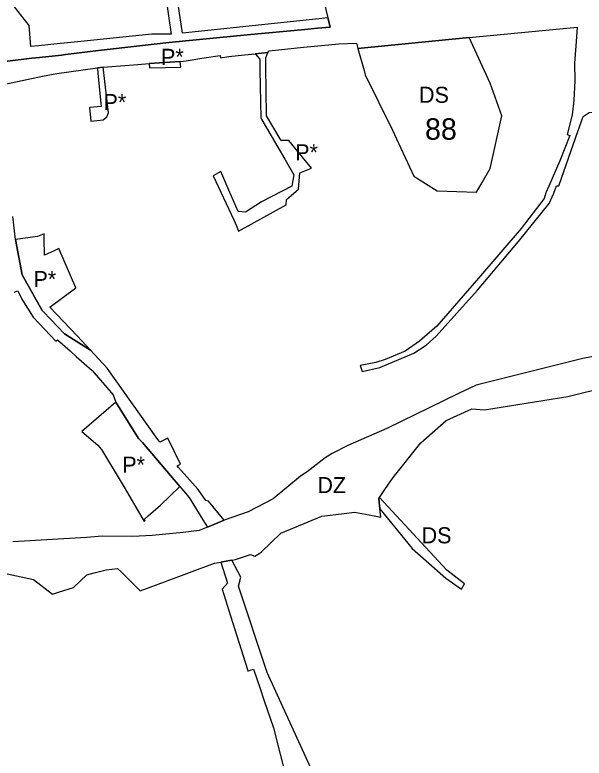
# Model space of a CAD drawing. Extents: x -477304 to -465641, y -1159113 to -1149285.
# Drawn here: x -475006.4 to -474687.6, y -1154553.8 to -1154137.8 of the extents above; entities that cross this region are included whole.
import ezdxf

# ---------------------------------------------------------------- set-up
doc = ezdxf.new("R2010")
doc.units = 0
for name, color, linetype in [('14', 7, 'Continuous'), ('22', 7, 'Continuous'), ('34', 7, 'Continuous'), ('35', 7, 'Continuous'), ('60', 7, 'Continuous')]:
    doc.layers.add(name, color=color, linetype=linetype)

msp = doc.modelspace()

# ---------------------------------------------------------------- linework, layer by layer
at = {"layer": '14'}
for p, q in [((-474752.01, -1154150.58), (-474814.35, -1154156.58)), ((-474814.35, -1154156.58), (-474810.87, -1154168.91)), ((-474810.87, -1154168.91), (-474810.16, -1154171.41)), ((-474810.16, -1154171.41), (-474795.13, -1154202.01)), ((-474795.13, -1154202.01), (-474783.06, -1154228.13)), ((-474783.06, -1154228.13), (-474769.99, -1154236.24)), ((-474769.99, -1154236.24), (-474747.97, -1154237.14))]:
    msp.add_line(p, q, dxfattribs=at)
msp.add_lwpolyline([(-474747.97, -1154237.14), (-474745.38, -1154232.64), (-474740.33, -1154223.86), (-474733.79, -1154194.37), (-474740.17, -1154176.02), (-474752.01, -1154150.58)], dxfattribs=at)
at = {"layer": '22'}
for p, q in [((-474636.13, -1154319.33), (-474688.28, -1154330.2)), ((-474688.28, -1154330.2), (-474748.09, -1154345.04)), ((-474748.09, -1154345.04), (-474757.89, -1154349.79)), ((-474757.89, -1154349.79), (-474798.19, -1154369.32)), ((-474798.19, -1154369.32), (-474819.91, -1154378.93)), ((-474819.91, -1154378.93), (-474828.71, -1154383.32)), ((-474832.7, -1154385.67), (-474842.67, -1154393.56)), ((-474828.71, -1154383.32), (-474832.7, -1154385.67)), ((-474842.67, -1154393.56), (-474846.54, -1154396.07)), ((-474846.54, -1154396.07), (-474861.86, -1154408.74)), ((-474802.64, -1154408.53), (-474802.25, -1154407.96)), ((-474861.86, -1154408.74), (-474875.74, -1154415.96)), ((-474801.95, -1154414.36), (-474802.64, -1154408.53)), ((-474875.74, -1154415.96), (-474889.28, -1154420.65)), ((-474801.42, -1154418.89), (-474801.95, -1154414.36)), ((-474889.28, -1154420.65), (-474898.52, -1154424.56)), ((-474834.49, -1154418.42), (-474822.1, -1154416.88)), ((-474808.03, -1154417.67), (-474801.42, -1154418.89)), ((-474912.16, -1154427.54), (-474929.44, -1154429.22)), ((-474966.39, -1154430.37), (-475007.64, -1154432.77)), ((-474957.5, -1154429.59), (-474966.39, -1154430.37)), ((-474940.42, -1154429.78), (-474957.5, -1154429.59)), ((-474929.44, -1154429.22), (-474940.42, -1154429.78)), ((-474922.64, -1154455.05), (-474894.65, -1154444.78)), ((-474887.14, -1154443.47), (-474884.96, -1154443.09)), ((-474884.96, -1154443.09), (-474882.94, -1154442.72)), ((-474948.89, -1154447.67), (-474946.91, -1154449.61)), ((-474966.13, -1154451.2), (-474961.93, -1154450.13)), ((-474926.11, -1154456.37), (-474922.64, -1154455.05))]:
    msp.add_line(p, q, dxfattribs=at)
for points in [[(-474696.72, -1154351.4), (-474674.85, -1154346.03), (-474671.91, -1154343.62)], [(-474764.95, -1154364.92), (-474750.55, -1154358.35), (-474743.38, -1154358.94), (-474696.72, -1154351.4)], [(-474794.59, -1154396.72), (-474778.99, -1154377.31), (-474764.95, -1154364.92)], [(-474802.25, -1154407.96), (-474799.2, -1154403.48), (-474794.59, -1154396.72)], [(-474822.1, -1154416.88), (-474816.22, -1154416.15), (-474808.03, -1154417.67)], [(-474871.97, -1154440.71), (-474869.64, -1154439.26), (-474868.48, -1154438.54), (-474857.42, -1154427.96), (-474834.49, -1154418.42)], [(-474898.52, -1154424.56), (-474903.26, -1154426.33), (-474912.16, -1154427.54)], [(-474882.94, -1154442.72), (-474874.45, -1154439.86), (-474871.97, -1154440.71)], [(-474894.65, -1154444.78), (-474892.28, -1154444.37), (-474891, -1154444.14), (-474887.14, -1154443.47)], [(-475045.61, -1154451.29), (-475041.55, -1154450.53), (-475015.25, -1154449.77), (-474995.98, -1154453.87), (-474985.43, -1154461.95), (-474982.07, -1154460.95)], [(-474961.93, -1154450.13), (-474955.3, -1154448.43), (-474948.89, -1154447.67)], [(-474946.91, -1154449.61), (-474936.22, -1154460.09), (-474926.11, -1154456.37)], [(-474982.07, -1154460.95), (-474973.56, -1154458.4), (-474966.13, -1154451.2)]]:
    msp.add_lwpolyline(points, dxfattribs=at)
at = {"layer": '34'}
for p, q in [((-474998.43, -1154143.87), (-475023.31, -1154111.7)), ((-474922.51, -1154123.49), (-474918.97, -1154148.69)), ((-474912.63, -1154148.06), (-474916.14, -1154123.06)), ((-474836.21, -1154140), (-474912.63, -1154148.06)), ((-474831.07, -1154139.46), (-474836.21, -1154140)), ((-474830.22, -1154143.01), (-474831.07, -1154139.46)), ((-474997.45, -1154155.62), (-474998.43, -1154143.87)), ((-474836.9, -1154145.37), (-474829.81, -1154144.78)), ((-474829.81, -1154144.78), (-474830.22, -1154143.01)), ((-474929.75, -1154148.72), (-474967.69, -1154152.57)), ((-474927.79, -1154148.61), (-474929.75, -1154148.72)), ((-474918.97, -1154148.69), (-474927.79, -1154148.61)), ((-474981.12, -1154153.94), (-474993.25, -1154155.18)), ((-474978.89, -1154153.71), (-474981.12, -1154153.94)), ((-474967.69, -1154152.57), (-474978.89, -1154153.71)), ((-474993.25, -1154155.18), (-474997.45, -1154155.62)), ((-474996.91, -1154162.11), (-474992.59, -1154161.64)), ((-474864.75, -1154158.93), (-474871.84, -1154159.58)), ((-474865.92, -1154161.91), (-474864.75, -1154158.93)), ((-474865.85, -1154166.97), (-474865.92, -1154161.91)), ((-474913.9, -1154164.02), (-474931.22, -1154165.12)), ((-474931.22, -1154165.12), (-474931.02, -1154167.44)), ((-474913.46, -1154167.06), (-474913.9, -1154164.02)), ((-474865.47, -1154193.74), (-474865.85, -1154166.97)), ((-474957.04, -1154167.07), (-474960.2, -1154167.52)), ((-474960.2, -1154167.52), (-474960.2, -1154167.52)), ((-474960.2, -1154167.52), (-474959.9, -1154170.72)), ((-474959.9, -1154170.72), (-474958.17, -1154189.06)), ((-474931.02, -1154167.44), (-474913.46, -1154167.06)), ((-474869.2, -1154168.66), (-474868.67, -1154195.48)), ((-474958.17, -1154189.06), (-474964.69, -1154189.67)), ((-474964.69, -1154189.67), (-474963.91, -1154197.35)), ((-474956.88, -1154196.61), (-474954.94, -1154194.94)), ((-474868.67, -1154195.48), (-474868.03, -1154196.59)), ((-474865.46, -1154194.26), (-474865.47, -1154193.74)), ((-474857.35, -1154208.18), (-474865.46, -1154194.26)), ((-474963.91, -1154197.35), (-474956.88, -1154196.61)), ((-474868.03, -1154196.59), (-474855.29, -1154218.56)), ((-474852.95, -1154208.16), (-474857.35, -1154208.18)), ((-474840.29, -1154223.59), (-474852.95, -1154208.16)), ((-474846.85, -1154226.22), (-474840.29, -1154223.59)), ((-474891.14, -1154225.46), (-474895.38, -1154227.96)), ((-474895.38, -1154227.96), (-474883.84, -1154252.63)), ((-474886.64, -1154236.03), (-474891.14, -1154225.46)), ((-474847.63, -1154235.42), (-474846.85, -1154226.22)), ((-474881.41, -1154247.97), (-474886.64, -1154236.03)), ((-474851.3, -1154233.77), (-474868.36, -1154242.41)), ((-474854.38, -1154241.09), (-474847.63, -1154235.42)), ((-474854.46, -1154244.15), (-474854.38, -1154241.09)), ((-474868.36, -1154242.41), (-474877.21, -1154248.23)), ((-474877.21, -1154248.23), (-474881.41, -1154247.97)), ((-474883.84, -1154252.63), (-474882.35, -1154255.86)), ((-474993.67, -1154261.9), (-475006.1, -1154263.62)), ((-474990.09, -1154260.41), (-474993.67, -1154261.9)), ((-474990.03, -1154262.98), (-474990.09, -1154260.41)), ((-474989.83, -1154272.25), (-474990.03, -1154262.98)), ((-474984.38, -1154269.84), (-474989.83, -1154272.25)), ((-474981.71, -1154268.66), (-474984.38, -1154269.84)), ((-474972.29, -1154290.63), (-474981.71, -1154268.66)), ((-474986.75, -1154301.43), (-474972.29, -1154290.63)), ((-474978.66, -1154316.39), (-474964.01, -1154325.56)), ((-474949.81, -1154354.63), (-474968.86, -1154370.98)), ((-474937.13, -1154374.91), (-474949.81, -1154354.63)), ((-474968.86, -1154370.98), (-474959.98, -1154378.6)), ((-474944.67, -1154403.09), (-474934.02, -1154421.36)), ((-474924.85, -1154412.2), (-474914.07, -1154401.83)), ((-474931.7, -1154418.24), (-474924.85, -1154412.2)), ((-474933.96, -1154420.21), (-474931.7, -1154418.24)), ((-474933.45, -1154420.8), (-474933.96, -1154420.21)), ((-474934.02, -1154421.36), (-474933.45, -1154420.8))]:
    msp.add_line(p, q, dxfattribs=at)
for points in [[(-474978.11, -1154160.06), (-474959.51, -1154157.75), (-474920.19, -1154153.37), (-474876.25, -1154148.96), (-474844.03, -1154145.97), (-474836.9, -1154145.37)], [(-475031.72, -1154164.64), (-475010.52, -1154163.84), (-474996.91, -1154162.11)], [(-474992.59, -1154161.64), (-474980.34, -1154160.31), (-474978.11, -1154160.06)], [(-474871.84, -1154159.58), (-474869.32, -1154162.56), (-474869.2, -1154168.66)], [(-474954.94, -1154194.94), (-474953.96, -1154192.6), (-474957.04, -1154167.07)], [(-474855.29, -1154218.56), (-474850.2, -1154227.37), (-474851.3, -1154233.77)], [(-474882.35, -1154255.86), (-474881.21, -1154258.81), (-474854.46, -1154244.15)], [(-475006.1, -1154263.62), (-475002.33, -1154283.3), (-474991.05, -1154303.37), (-474990.34, -1154304.11), (-474978.66, -1154316.39)], [(-474964.01, -1154325.56), (-474971.46, -1154317.51), (-474986.75, -1154301.43)], [(-474914.07, -1154401.83), (-474934.98, -1154377.19), (-474937.13, -1154374.91)], [(-474959.98, -1154378.6), (-474957.84, -1154381.15), (-474944.67, -1154403.09)]]:
    msp.add_lwpolyline(points, dxfattribs=at)
at = {"layer": '35'}
for p, q in [((-474829.81, -1154144.78), (-474836.9, -1154145.37)), ((-474830.22, -1154143.01), (-474829.81, -1154144.78)), ((-474752.01, -1154150.58), (-474691.62, -1154144.65)), ((-474691.62, -1154144.65), (-474692.18, -1154152.78)), ((-474834.67, -1154155.03), (-474825.01, -1154154.1)), ((-474825.01, -1154154.1), (-474815.16, -1154153.73)), ((-474815.16, -1154153.73), (-474814.35, -1154156.58)), ((-474814.35, -1154156.58), (-474752.01, -1154150.58)), ((-474864.75, -1154158.93), (-474864, -1154157.88)), ((-474864, -1154157.88), (-474844.76, -1154156)), ((-474844.76, -1154156), (-474834.67, -1154155.03)), ((-474992.59, -1154161.64), (-474996.91, -1154162.11)), ((-474910.53, -1154163.49), (-474901.72, -1154162.12)), ((-474901.72, -1154162.12), (-474891.41, -1154160.6)), ((-474891.41, -1154160.6), (-474891.22, -1154161.79)), ((-474891.22, -1154161.79), (-474886.63, -1154161.16)), ((-474886.63, -1154161.16), (-474877.89, -1154160.26)), ((-474877.89, -1154160.26), (-474871.84, -1154159.58)), ((-474871.84, -1154159.58), (-474864.75, -1154158.93)), ((-474913.9, -1154164.02), (-474910.53, -1154163.49)), ((-474990.96, -1154172.13), (-474982.97, -1154170.73)), ((-474982.97, -1154170.73), (-474960.2, -1154167.52)), ((-474960.2, -1154167.52), (-474957.04, -1154167.07)), ((-474960.2, -1154167.52), (-474960.2, -1154167.52)), ((-475011.15, -1154176.45), (-474990.96, -1154172.13)), ((-474694.4, -1154193.76), (-474697.06, -1154204.88)), ((-474692.35, -1154206.36), (-474688.25, -1154194.79)), ((-474701.71, -1154233.46), (-474692.35, -1154206.36)), ((-474697.06, -1154204.88), (-474695.55, -1154205.35)), ((-474704.64, -1154237.67), (-474703.11, -1154233.52)), ((-474703.11, -1154233.52), (-474701.71, -1154233.46)), ((-474709.05, -1154237.51), (-474710.08, -1154240.61)), ((-474707.39, -1154233.69), (-474709.05, -1154237.51)), ((-474707.25, -1154243.32), (-474704.64, -1154237.67)), ((-474724.31, -1154264.62), (-474707.25, -1154243.32)), ((-475006.1, -1154263.62), (-475007.51, -1154250.63)), ((-475006.75, -1154292.96), (-475004.72, -1154292.28)), ((-475004.72, -1154292.28), (-475002.56, -1154296.94)), ((-475002.56, -1154296.94), (-474996.14, -1154307.09)), ((-474996.14, -1154307.09), (-474983.41, -1154320.49)), ((-474770.1, -1154312.08), (-474779.76, -1154320.47)), ((-474964.01, -1154325.56), (-474978.66, -1154316.39)), ((-474776.12, -1154322.78), (-474770.41, -1154317.73)), ((-474782.92, -1154327.15), (-474776.12, -1154322.78)), ((-474975.4, -1154325.82), (-474972.12, -1154328.94)), ((-474972.12, -1154328.94), (-474963.09, -1154336.81)), ((-474954.69, -1154335.64), (-474964.01, -1154325.56)), ((-474802.07, -1154335.24), (-474782.92, -1154327.15)), ((-474804.35, -1154332.44), (-474813.14, -1154334.09)), ((-474963.09, -1154336.81), (-474951.42, -1154350.53)), ((-474927.26, -1154374.09), (-474954.69, -1154335.64)), ((-474951.42, -1154350.53), (-474949.81, -1154354.63)), ((-474949.81, -1154354.63), (-474937.13, -1154374.91)), ((-474925.33, -1154376.94), (-474927.26, -1154374.09)), ((-474920.84, -1154374.74), (-474925.33, -1154376.94)), ((-474913.61, -1154389.33), (-474920.84, -1154374.74)), ((-474915.48, -1154390.25), (-474913.61, -1154389.33)), ((-474914.76, -1154391.06), (-474915.48, -1154390.25)), ((-474903.79, -1154403.46), (-474914.76, -1154391.06)), ((-474899.44, -1154409.69), (-474903.79, -1154403.46)), ((-474908.85, -1154407.89), (-474901.08, -1154420.47)), ((-474764.55, -1154448.68), (-474802.25, -1154407.96)), ((-474898.03, -1154410.02), (-474899.44, -1154409.69)), ((-474890.08, -1154419.47), (-474898.03, -1154410.02)), ((-474901.08, -1154420.47), (-474898.52, -1154424.56)), ((-474898.52, -1154424.56), (-474889.28, -1154420.65)), ((-474889.28, -1154420.65), (-474890.08, -1154419.47)), ((-474884.96, -1154443.09), (-474887.14, -1154443.47)), ((-474879.84, -1154452.46), (-474884.96, -1154443.09)), ((-474754.62, -1154456.2), (-474764.55, -1154448.68)), ((-474881.14, -1154457.62), (-474879.84, -1154452.46)), ((-474765.05, -1154453.09), (-474756.31, -1154459.25)), ((-474887.41, -1154455.88), (-474890.29, -1154459.26)), ((-474865.21, -1154505.85), (-474881.14, -1154457.62)), ((-474756.31, -1154459.25), (-474754.62, -1154456.2)), ((-474890.29, -1154459.26), (-474885.74, -1154474.21)), ((-474872.7, -1154503.95), (-474869.12, -1154514.77)), ((-474869.12, -1154514.77), (-474866.99, -1154521.22)), ((-474866.99, -1154521.22), (-474861.66, -1154536.87))]:
    msp.add_line(p, q, dxfattribs=at)
for points in [[(-474837.45, -1154112.7), (-474835.74, -1154119.87), (-474831.07, -1154139.46), (-474830.22, -1154143.01)], [(-474836.9, -1154145.37), (-474844.03, -1154145.97), (-474876.25, -1154148.96), (-474920.19, -1154153.37), (-474959.51, -1154157.75), (-474978.11, -1154160.06)], [(-474692.18, -1154152.78), (-474693.03, -1154164.95), (-474692.84, -1154174.69)], [(-474996.91, -1154162.11), (-475010.52, -1154163.84), (-475031.72, -1154164.64)], [(-474978.11, -1154160.06), (-474980.34, -1154160.31), (-474992.59, -1154161.64)], [(-474957.04, -1154167.07), (-474937.48, -1154165.64), (-474931.22, -1154165.12), (-474913.9, -1154164.02)], [(-474692.84, -1154174.69), (-474693.37, -1154185.62), (-474694.4, -1154193.76)], [(-474688.25, -1154194.79), (-474684.83, -1154192.42), (-474680.03, -1154191.9)], [(-474695.55, -1154205.35), (-474701.24, -1154219.56), (-474707.39, -1154233.69)], [(-474710.08, -1154240.61), (-474722.98, -1154257.4), (-474746.69, -1154285.2), (-474770.1, -1154312.08)], [(-474978.66, -1154316.39), (-474990.34, -1154304.11), (-474991.05, -1154303.37), (-475002.33, -1154283.3), (-475006.1, -1154263.62)], [(-474770.41, -1154317.73), (-474747.43, -1154291.98), (-474724.31, -1154264.62)], [(-474983.41, -1154320.49), (-474982.51, -1154319.72), (-474975.4, -1154325.82)], [(-474779.76, -1154320.47), (-474787.78, -1154326), (-474799.05, -1154330.78), (-474804.35, -1154332.44)], [(-474813.14, -1154334.09), (-474811.98, -1154337.48), (-474802.07, -1154335.24)], [(-474937.13, -1154374.91), (-474934.98, -1154377.19), (-474914.07, -1154401.83), (-474908.85, -1154407.89)], [(-474802.25, -1154407.96), (-474802.64, -1154408.53), (-474801.95, -1154414.36), (-474783.9, -1154436.41), (-474765.05, -1154453.09)], [(-474887.14, -1154443.47), (-474891, -1154444.14), (-474887.41, -1154455.88)], [(-474885.74, -1154474.21), (-474876.19, -1154504.11), (-474875.89, -1154505.06)], [(-474875.89, -1154505.06), (-474874, -1154504.4), (-474872.7, -1154503.95)], [(-474839.4, -1154562.29), (-474860.32, -1154516.54), (-474865.21, -1154505.85)], [(-474861.66, -1154536.87), (-474850.4, -1154581), (-474828.11, -1154638.77)]]:
    msp.add_lwpolyline(points, dxfattribs=at)

# ---------------------------------------------------------------- texts
at = {"layer": '14'}
msp.add_text('DS', height=9, dxfattribs=at).set_placement((-474780.08, -1154187.06))
at = {"layer": '22'}
msp.add_text('DZ', height=9, dxfattribs=at).set_placement((-474836.99, -1154405.5))
at = {"layer": '34'}
for p in [(-474924.56, -1154165.83), (-474956.75, -1154191.17), (-474849.39, -1154219.27), (-474995.98, -1154290.21), (-474946.25, -1154394.1)]:
    msp.add_text('P*', height=9, dxfattribs=at).set_placement(p)
at = {"layer": '35'}
msp.add_text('DS', height=9, dxfattribs=at).set_placement((-474778.63, -1154433.6))
at = {"layer": '60'}
msp.add_text('88', height=12, dxfattribs=at).set_placement((-474776.75, -1154207.71))

doc.saveas('drawing.dxf')
